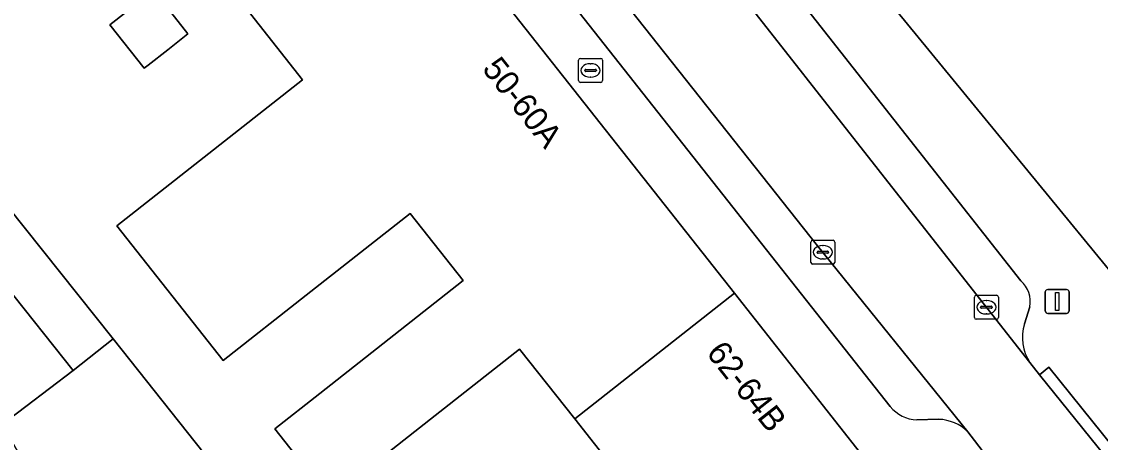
# Model space of a CAD drawing. Extents: x 160663 to 161506, y 382245 to 383291.
# Drawn here: x 160906.51 to 160951.59, y 382958.1 to 382975.7 of the extents above; entities that cross this region are included whole.
import ezdxf

# ---------------------------------------------------------------- set-up
doc = ezdxf.new("R2010")
doc.units = 0
for name, color, linetype in [('IMGEO_Brandkraan', 7, 'Continuous'), ('IMGEO_Erf', 7, 'Continuous'), ('IMGEO_Kolk', 7, 'Continuous'), ('IMGEO_Lichtmast', 7, 'Continuous'), ('IMGEO_Pand', 7, 'Continuous'), ('IMGEO_Pand_nummerreeks', 7, 'Continuous'), ('IMGEO_Parkeervlak_open', 7, 'Continuous'), ('IMGEO_Rijbaan_lokaal_open', 7, 'Continuous'), ('IMGEO_Voetpad_open', 7, 'Continuous')]:
    doc.layers.add(name, color=color, linetype=linetype)

msp = doc.modelspace()

# ---------------------------------------------------------------- linework, layer by layer
at = {"layer": 'IMGEO_Brandkraan'}
for p, q in [((160929.787, 382973.233), (160929.787, 382974.085)), ((160929.862, 382974.159), (160930.714, 382974.159)), ((160930.788, 382974.085), (160930.788, 382973.233)), ((160930.046, 382973.653), (160930.046, 382973.665)), ((160930.484, 382973.616), (160930.086, 382973.616)), ((160930.089, 382973.702), (160930.487, 382973.702)), ((160930.275, 382973.939), (160930.3, 382973.939)), ((160930.53, 382973.665), (160930.53, 382973.653)), ((160930.714, 382973.159), (160929.862, 382973.159)), ((160930.298, 382973.379), (160930.273, 382973.379))]:
    msp.add_line(p, q, dxfattribs=at)
for points in [[(160929.787, 382973.233), (160929.787, 382974.085)], [(160929.862, 382974.159), (160930.714, 382974.159)], [(160930.788, 382974.085), (160930.788, 382973.233)], [(160930.714, 382973.159), (160929.862, 382973.159)]]:
    msp.add_lwpolyline(points, dxfattribs=at)
for centre, radius, start, end in [((160929.864, 382974.083), 0.0765, 91.552, 178.448), ((160929.864, 382974.083), 0.0765, 91.552, 178.448), ((160930.712, 382974.083), 0.0765, 1.552, 88.448), ((160930.712, 382974.083), 0.0765, 1.552, 88.448), ((160930.086, 382973.662), 0.0403, 85.8775, 175.7526), ((160930.083, 382973.652), 0.0366, 178.938, 274.7102), ((160930.487, 382973.659), 0.043, 264.8664, 352.4533), ((160930.491, 382973.664), 0.0386, 1.7309, 96.639), ((160929.864, 382973.235), 0.0765, 181.552, 268.448), ((160929.864, 382973.235), 0.0765, 181.552, 268.448), ((160930.712, 382973.235), 0.0765, 271.552, 358.448), ((160930.712, 382973.235), 0.0765, 271.552, 358.448)]:
    msp.add_arc(centre, radius, start, end, dxfattribs=at)
for centre, major_axis, ratio, start_param, end_param in [((160930.274, 382973.659), (-0.387, 0.002), 0.722429, 4.712389, 7.853982), ((160930.299, 382973.659), (-0.39, 0.002), 0.717154, 1.570796, 4.712389)]:
    msp.add_ellipse(centre, major_axis=major_axis, ratio=ratio, start_param=start_param, end_param=end_param, dxfattribs=at)
at = {"layer": 'IMGEO_Erf'}
msp.add_lwpolyline([(160910.207, 382975.568), (160912.037, 382977.01), (160913.467, 382975.195), (160912.62, 382974.527), (160911.805, 382973.885), (160911.637, 382973.753)], close=True, dxfattribs=at)
for points in [[(160931.94, 382956.146), (160929.626, 382959.081), (160927.325, 382962.001), (160922.946, 382958.549), (160919.394, 382955.749), (160917.095, 382958.667), (160918.978, 382960.151), (160924.959, 382964.865), (160922.745, 382967.673), (160918.411, 382964.257), (160914.937, 382961.519), (160910.495, 382967.154), (160913.945, 382969.874), (160918.254, 382973.271), (160916.084, 382976.025)], [(160905.909, 382967.992), (160910.338, 382962.425), (160917.249, 382953.72)], [(160905.808, 382954.621), (160908.104, 382954.357), (160908.24, 382954.436), (160905.706, 382958.852), (160908.677, 382961.103), (160905.809, 382964.709)]]:
    msp.add_lwpolyline(points, dxfattribs=at)
at = {"layer": 'IMGEO_Kolk'}
for p, q in [((160939.492, 382965.628), (160939.492, 382966.48)), ((160939.567, 382966.554), (160940.419, 382966.554)), ((160940.493, 382966.48), (160940.493, 382965.628)), ((160939.751, 382966.048), (160939.751, 382966.06)), ((160940.189, 382966.011), (160939.791, 382966.011)), ((160939.794, 382966.097), (160940.192, 382966.097)), ((160939.98, 382966.334), (160940.005, 382966.334)), ((160940.235, 382966.06), (160940.235, 382966.048)), ((160940.419, 382965.554), (160939.567, 382965.554)), ((160940.003, 382965.774), (160939.978, 382965.774)), ((160946.326, 382963.327), (160946.326, 382964.179)), ((160946.401, 382964.253), (160947.253, 382964.253)), ((160947.327, 382964.179), (160947.327, 382963.327)), ((160946.585, 382963.747), (160946.585, 382963.759)), ((160947.023, 382963.71), (160946.625, 382963.71)), ((160946.628, 382963.796), (160947.026, 382963.796)), ((160946.814, 382964.033), (160946.839, 382964.033)), ((160947.069, 382963.759), (160947.069, 382963.747)), ((160947.253, 382963.253), (160946.401, 382963.253)), ((160946.837, 382963.473), (160946.812, 382963.473))]:
    msp.add_line(p, q, dxfattribs=at)
for points in [[(160939.492, 382965.628), (160939.492, 382966.48)], [(160939.567, 382966.554), (160940.419, 382966.554)], [(160940.493, 382966.48), (160940.493, 382965.628)], [(160940.419, 382965.554), (160939.567, 382965.554)], [(160946.326, 382963.327), (160946.326, 382964.179)], [(160946.401, 382964.253), (160947.253, 382964.253)], [(160947.327, 382964.179), (160947.327, 382963.327)], [(160947.253, 382963.253), (160946.401, 382963.253)]]:
    msp.add_lwpolyline(points, dxfattribs=at)
for centre, radius, start, end in [((160939.569, 382966.478), 0.0765, 91.552, 178.448), ((160939.569, 382966.478), 0.0765, 91.552, 178.448), ((160940.417, 382966.478), 0.0765, 1.552, 88.448), ((160940.417, 382966.478), 0.0765, 1.552, 88.448), ((160939.791, 382966.057), 0.0403, 85.8775, 175.7526), ((160939.788, 382966.047), 0.0366, 178.938, 274.7102), ((160940.192, 382966.054), 0.043, 264.8664, 352.4533), ((160940.196, 382966.059), 0.0386, 1.7309, 96.639), ((160939.569, 382965.63), 0.0765, 181.552, 268.448), ((160939.569, 382965.63), 0.0765, 181.552, 268.448), ((160940.417, 382965.63), 0.0765, 271.552, 358.448), ((160940.417, 382965.63), 0.0765, 271.552, 358.448), ((160946.403, 382964.177), 0.0765, 91.552, 178.448), ((160946.403, 382964.177), 0.0765, 91.552, 178.448), ((160947.251, 382964.177), 0.0765, 1.552, 88.448), ((160947.251, 382964.177), 0.0765, 1.552, 88.448), ((160946.625, 382963.756), 0.0403, 85.8775, 175.7526), ((160946.622, 382963.746), 0.0366, 178.938, 274.7102), ((160947.026, 382963.753), 0.043, 264.8664, 352.4533), ((160947.03, 382963.758), 0.0386, 1.7309, 96.639), ((160946.403, 382963.329), 0.0765, 181.552, 268.448), ((160946.403, 382963.329), 0.0765, 181.552, 268.448), ((160947.251, 382963.329), 0.0765, 271.552, 358.448), ((160947.251, 382963.329), 0.0765, 271.552, 358.448)]:
    msp.add_arc(centre, radius, start, end, dxfattribs=at)
for centre, major_axis, ratio, start_param, end_param in [((160939.979, 382966.054), (-0.387, 0.002), 0.722429, 4.712389, 7.853982), ((160940.004, 382966.054), (-0.39, 0.002), 0.717154, 1.570796, 4.712389), ((160946.813, 382963.753), (-0.387, 0.002), 0.722429, 4.712389, 7.853982), ((160946.838, 382963.753), (-0.39, 0.002), 0.717154, 1.570796, 4.712389)]:
    msp.add_ellipse(centre, major_axis=major_axis, ratio=ratio, start_param=start_param, end_param=end_param, dxfattribs=at)
at = {"layer": 'IMGEO_Lichtmast'}
for p, q in [((160949.287, 382963.595), (160949.287, 382964.395)), ((160949.287, 382964.395), (160949.287, 382963.595)), ((160949.387, 382964.495), (160950.177, 382964.495)), ((160950.177, 382964.495), (160949.387, 382964.495)), ((160950.277, 382964.395), (160950.277, 382963.595)), ((160950.277, 382963.595), (160950.277, 382964.395)), ((160950.177, 382963.495), (160949.387, 382963.495)), ((160949.387, 382963.495), (160950.177, 382963.495))]:
    msp.add_line(p, q, dxfattribs=at)
msp.add_lwpolyline([(160949.707, 382964.37), (160949.857, 382964.37), (160949.857, 382963.62), (160949.707, 382963.62), (160949.707, 382964.37)], dxfattribs=at)
for centre, start, end in [((160949.387, 382964.395), 90, 180), ((160949.387, 382964.395), 90, 180), ((160950.177, 382964.395), 0, 90), ((160950.177, 382964.395), 360, 90), ((160949.387, 382963.595), 180, 270), ((160949.387, 382963.595), 180, 270), ((160950.177, 382963.595), 270, 0), ((160950.177, 382963.595), 270, 0)]:
    msp.add_arc(centre, 0.1, start, end, dxfattribs=at)
at = {"layer": 'IMGEO_Pand'}
for points in [[(160936.91, 383000), (160925.377, 383014.054), (160925.308, 383014.138), (160917.332, 383007.56), (160917.629, 383007.213), (160923.54, 383000), (160953.589, 382963.329), (160961.617, 382969.937), (160958.423, 382973.784)], [(160922.745, 382967.673), (160924.959, 382964.865), (160918.978, 382960.151), (160917.095, 382958.667), (160919.394, 382955.749), (160922.946, 382958.549), (160927.325, 382962.001), (160929.626, 382959.081), (160936.296, 382964.339), (160922.87, 382981.373), (160918.943, 382978.278), (160916.084, 382976.025), (160918.254, 382973.271), (160913.945, 382969.874), (160910.495, 382967.154), (160914.937, 382961.519), (160918.411, 382964.257)], [(160910.207, 382975.568), (160911.637, 382973.753), (160911.805, 382973.885), (160912.62, 382974.527), (160913.467, 382975.195), (160912.037, 382977.01)], [(160908.677, 382961.103), (160910.338, 382962.425), (160905.909, 382967.992), (160901.649, 382964.603), (160903.21, 382962.641), (160905.809, 382964.709)], [(160941.208, 382956.231), (160941.569, 382957.648), (160936.296, 382964.339), (160929.626, 382959.081), (160931.94, 382956.146), (160924.572, 382952.401), (160926.577, 382948.746), (160930.62, 382950.8), (160930.705, 382950.633), (160931.606, 382951.091), (160931.5, 382951.298)], [(160908.677, 382961.103), (160905.706, 382958.852), (160908.24, 382954.436), (160914.869, 382942.835), (160921.539, 382946.213), (160917.249, 382953.72), (160910.338, 382962.425)]]:
    msp.add_lwpolyline(points, close=True, dxfattribs=at)
at = {"layer": 'IMGEO_Parkeervlak_open'}
for points in [[(160913.779, 383005.798), (160918.437, 383000), (160918.803, 382999.544), (160924.797, 382991.941), (160933.124, 382981.221), (160945.313, 382965.677), (160948.644, 382961.441)], [(160912.693, 382997.808), (160942.811, 382959.598)], [(160946.054, 382958.546), (160939.776, 382966.323), (160931.369, 382976.952), (160924.054, 382986.182)], [(160948.265, 382964.86), (160935.436, 382981.183)], [(160948.423, 382963.057), (160948.641, 382963.767)], [(160943.921, 382959.04), (160944.83, 382959.064)]]:
    msp.add_lwpolyline(points, dxfattribs=at)
for centre, radius, start, end in [((160947.51, 382963.989), 1.152, 348.8771, 49.0901), ((160950.201, 382962.477), 1.87, 161.9342, 213.6404), ((160943.998, 382960.576), 1.538, 219.4887, 267.1337), ((160944.766, 382957.207), 1.858, 46.1032, 88.0204)]:
    msp.add_arc(centre, radius, start, end, dxfattribs=at)
at = {"layer": 'IMGEO_Rijbaan_lokaal_open'}
for points in [[(160910.123, 383004.736), (160911.875, 383001.803), (160912.174, 383001.388), (160912.505, 383000.929), (160913.236, 383000), (160915.288, 382997.392), (160924.054, 382986.182), (160931.369, 382976.952), (160939.776, 382966.323), (160946.054, 382958.546), (160949.734, 382953.736)], [(160954.79, 382953.789), (160952.666, 382956.429), (160949.045, 382960.931), (160948.644, 382961.441), (160945.313, 382965.677), (160933.124, 382981.221), (160924.797, 382991.941)]]:
    msp.add_lwpolyline(points, dxfattribs=at)
at = {"layer": 'IMGEO_Voetpad_open'}
for points in [[(160948.644, 382961.441), (160949.045, 382960.931), (160949.433, 382961.245), (160953.054, 382956.743), (160956.597, 382959.624), (160956.311, 382959.971), (160953.589, 382963.329), (160923.54, 383000), (160917.629, 383007.213), (160917.332, 383007.56), (160916.974, 383007.978), (160916.747, 383007.941), (160916.14, 383011.661)], [(160915.259, 383006.315), (160920.52, 383000), (160931.336, 382986.457), (160935.436, 382981.183), (160948.265, 382964.86)], [(160906.371, 383001.946), (160906.884, 383001.343), (160907.225, 383001.304), (160908.012, 383000.311), (160907.888, 383000.213), (160908.057, 383000), (160910.247, 382997.239), (160912.707, 382994.137), (160912.982, 382994.176), (160914.43, 382992.339), (160915.788, 382990.616), (160915.709, 382990.419), (160918.2, 382987.258), (160922.268, 382982.132), (160922.87, 382981.373), (160936.296, 382964.339), (160941.569, 382957.648), (160943.18, 382954.261), (160946.201, 382950.273), (160946.345, 382949.934), (160945.757, 382939.672), (160945.978, 382935.062), (160946.296, 382935.03)], [(160942.811, 382959.598), (160912.693, 382997.808)], [(160948.641, 382963.767), (160948.423, 382963.057)], [(160944.83, 382959.064), (160943.921, 382959.04)], [(160949.734, 382953.736), (160946.054, 382958.546)]]:
    msp.add_lwpolyline(points, dxfattribs=at)
msp.add_lwpolyline([(160949.045, 382960.931), (160952.666, 382956.429), (160953.054, 382956.743), (160949.433, 382961.245)], close=True, dxfattribs=at)
for centre, radius, start, end in [((160947.51, 382963.989), 1.152, 348.8771, 49.0901), ((160950.201, 382962.477), 1.87, 161.9342, 213.6404), ((160943.998, 382960.576), 1.538, 219.4887, 267.1337), ((160944.766, 382957.207), 1.858, 46.1032, 88.0204)]:
    msp.add_arc(centre, radius, start, end, dxfattribs=at)

# ---------------------------------------------------------------- texts
at = {"layer": 'IMGEO_Pand_nummerreeks'}
for s, rotation, p in [('50-60A', 308.2447, (160925.724, 382973.714)), ('62-64B', 308.239, (160935.09, 382961.831))]:
    msp.add_text(s, height=1, rotation=rotation, dxfattribs=at).set_placement(p)

doc.saveas('drawing.dxf')
